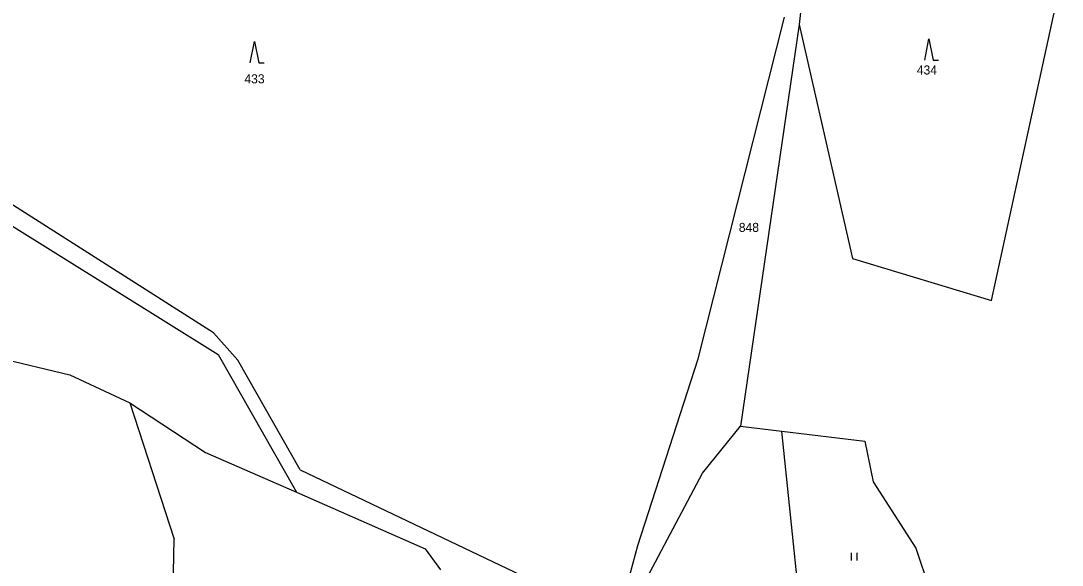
# Model space of a CAD drawing. Extents: x -791032 to -787751, y -1106872 to -1104403.
# Drawn here: x -789231 to -789035.3, y -1105041.7 to -1104939.4 of the extents above; entities that cross this region are included whole.
import ezdxf

# ---------------------------------------------------------------- set-up
doc = ezdxf.new("R2010")
doc.units = 0
for name, color, linetype in [('Vrstva 1', 7, 'Continuous'), ('Vrstva 14', 7, 'Continuous'), ('Vrstva 23', 7, 'Continuous')]:
    doc.layers.add(name, color=color, linetype=linetype)

msp = doc.modelspace()

# ---------------------------------------------------------------- linework, layer by layer
at = {"layer": 'Vrstva 1'}
for p, q in [((-789080.69, -1104904.37), (-789084.72, -1104940.08)), ((-789048.55, -1104991.98), (-789035.27, -1104931.1)), ((-789103.68, -1105002.93), (-789087.45, -1104938.74)), ((-789084.72, -1104940.08), (-789095.73, -1105015.58)), ((-789084.72, -1104940.08), (-789074.72, -1104984.06)), ((-789194.82, -1104998.08), (-789233.09, -1104973.66)), ((-789233.79, -1104977.26), (-789193.97, -1105002.1)), ((-789074.72, -1104984.06), (-789048.55, -1104991.98)), ((-789190.25, -1105003.2), (-789194.82, -1104998.08)), ((-789240.88, -1105001.4), (-789221.84, -1105005.93)), ((-789193.97, -1105002.1), (-789179.25, -1105028.02)), ((-789115.06, -1105038.01), (-789103.68, -1105002.93)), ((-789178.54, -1105023.79), (-789190.25, -1105003.2)), ((-789221.84, -1105005.93), (-789210.54, -1105011.23)), ((-789210.54, -1105011.23), (-789196.3, -1105020.53)), ((-789210.54, -1105011.23), (-789202.19, -1105036.83)), ((-789102.89, -1105024.45), (-789095.73, -1105015.58)), ((-789095.73, -1105015.58), (-789087.95, -1105016.54)), ((-789082, -1105074.19), (-789087.95, -1105016.54)), ((-789087.95, -1105016.54), (-789072.4, -1105018.45)), ((-789072.4, -1105018.45), (-789070.81, -1105026.07)), ((-789196.3, -1105020.53), (-789179.25, -1105028.02)), ((-789178.54, -1105023.79), (-789119.8, -1105051.77)), ((-789113.36, -1105044.2), (-789102.89, -1105024.45)), ((-789070.81, -1105026.07), (-789062.79, -1105038.52)), ((-789179.25, -1105028.02), (-789155.02, -1105038.66)), ((-789202.43, -1105048.85), (-789202.19, -1105036.83)), ((-789118.67, -1105051.32), (-789115.06, -1105038.01)), ((-789155.02, -1105038.66), (-789152.12, -1105042.62)), ((-789062.79, -1105038.52), (-789055.49, -1105059.88))]:
    msp.add_line(p, q, dxfattribs=at)
at = {"layer": 'Vrstva 23'}
for p, q in [((-789187.92, -1104947.29), (-789187.12, -1104943.29)), ((-789187.12, -1104943.29), (-789186.32, -1104947.29)), ((-789061.11, -1104946.8), (-789060.31, -1104942.8)), ((-789060.31, -1104942.8), (-789059.51, -1104946.8)), ((-789186.32, -1104947.29), (-789185.32, -1104947.29)), ((-789059.51, -1104946.8), (-789058.51, -1104946.8)), ((-789074.9, -1105040.88), (-789074.9, -1105039.38)), ((-789073.9, -1105039.38), (-789073.9, -1105040.88))]:
    msp.add_line(p, q, dxfattribs=at)

# ---------------------------------------------------------------- texts
at = {"layer": 'Vrstva 14'}
for s, p in [('434', (-789062.598, -1104949.5)), ('433', (-789189.013, -1104951.16)), ('848', (-789096.062, -1104979.09))]:
    msp.add_text(s, height=1.7, dxfattribs=at).set_placement(p)

doc.saveas('drawing.dxf')
